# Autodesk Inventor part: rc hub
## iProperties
Created: 2005-11
Part Number: rc hub
Document SubType Name: Modeling
Designer: Paul
Author: Paul
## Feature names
1. Extrusion1
2. Extrusion2
3. Chamfer1
4. Chamfer2
5. Chamfer3
6. Extrusion3
7. Chamfer4
